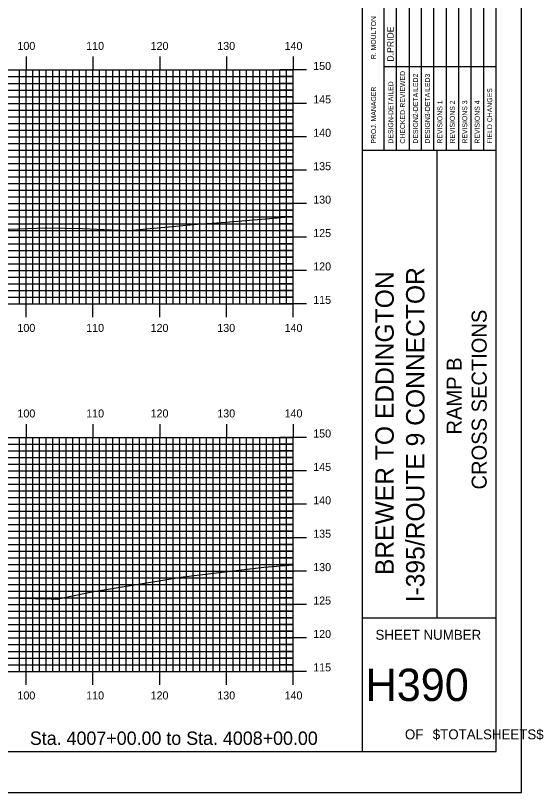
# Model space of a CAD drawing. Extents: x 851753 to 852097, y 364661 to 364881.
# Drawn here: x 852017.6 to 852096.7, y 364661.3 to 364777.5 of the extents above; entities that cross this region are included whole.
import ezdxf

# ---------------------------------------------------------------- set-up
doc = ezdxf.new("R2010")
doc.units = 0
for name, color, linetype in [('BORDER', 7, 'Continuous'), ('H_V ANNOTATION', 7, 'Continuous'), ('MAJOR', 7, 'Continuous'), ('MINOR', 7, 'Continuous'), ('PLOT BOUNDARY', 7, 'Continuous'), ('S_Roadway_Centerline', 7, 'Continuous')]:
    doc.layers.add(name, color=color, linetype=linetype)

msp = doc.modelspace()

# ---------------------------------------------------------------- linework, layer by layer
at = {"layer": 'BORDER'}
for p, q in [((852069.64, 364667.37), (852069.64, 364877.37)), ((852069.64, 364757.38), (852089.64, 364757.38)), ((852080.82, 364687.38), (852080.82, 364757.38)), ((852069.64, 364687.38), (852089.64, 364687.38))]:
    msp.add_line(p, q, dxfattribs=at)
msp.add_lwpolyline([(851769.64, 364667.37), (852089.64, 364667.37), (852089.64, 364877.37), (851769.64, 364877.37)], close=True, dxfattribs=at)
for points in [[(852074.74, 364757.38), (852074.74, 364792.38)], [(852076.6, 364792.38), (852076.6, 364757.38)], [(852078.46, 364757.38), (852078.46, 364792.38)], [(852080.33, 364757.38), (852080.33, 364792.38)], [(852082.19, 364757.38), (852082.19, 364792.38)], [(852084.05, 364757.38), (852084.05, 364792.38)], [(852085.92, 364757.38), (852085.92, 364792.38)], [(852087.78, 364757.38), (852087.78, 364792.38)], [(852072.87, 364757.38), (852072.87, 364790.96)], [(852072.87, 364769.88), (852089.64, 364769.88)]]:
    msp.add_lwpolyline(points, dxfattribs=at)
at = {"layer": 'MAJOR'}
for p, q in [((852019.24, 364771.37), (852019.24, 364769.37)), ((852029.24, 364771.37), (852029.24, 364769.37)), ((852039.24, 364771.37), (852039.24, 364769.37)), ((852049.24, 364771.37), (852049.24, 364769.37)), ((852059.24, 364771.37), (852059.24, 364769.37)), ((851779.24, 364769.37), (852059.24, 364769.37)), ((851779.24, 364769.37), (852059.24, 364769.37)), ((852019.24, 364734.37), (852019.24, 364769.37)), ((852029.24, 364734.37), (852029.24, 364769.37)), ((852039.24, 364734.37), (852039.24, 364769.37)), ((852049.24, 364734.37), (852049.24, 364769.37)), ((852061.25, 364769.37), (852057.24, 364769.37)), ((852059.24, 364734.37), (852059.24, 364769.37)), ((852059.24, 364734.37), (852059.24, 364769.37)), ((851779.24, 364764.37), (852059.24, 364764.37)), ((852061.25, 364764.37), (852057.24, 364764.37)), ((851779.24, 364759.37), (852059.24, 364759.37)), ((852061.25, 364759.37), (852057.24, 364759.37)), ((851779.24, 364754.37), (852059.24, 364754.37)), ((852061.25, 364754.37), (852057.24, 364754.37)), ((851779.24, 364749.37), (852059.24, 364749.37)), ((852061.25, 364749.37), (852057.24, 364749.37)), ((851779.24, 364744.37), (852059.24, 364744.37)), ((852061.25, 364744.37), (852057.24, 364744.37)), ((851779.24, 364739.37), (852059.24, 364739.37)), ((852061.25, 364739.37), (852057.24, 364739.37)), ((851779.24, 364734.37), (852059.24, 364734.37)), ((851779.24, 364734.37), (852059.24, 364734.37)), ((852019.24, 364732.37), (852019.24, 364734.37)), ((852029.24, 364732.37), (852029.24, 364734.37)), ((852039.24, 364732.37), (852039.24, 364734.37)), ((852049.24, 364732.37), (852049.24, 364734.37)), ((852061.25, 364734.37), (852057.24, 364734.37)), ((852059.24, 364732.37), (852059.24, 364734.37)), ((852019.24, 364716.37), (852019.24, 364714.37)), ((852029.24, 364716.37), (852029.24, 364714.37)), ((852039.24, 364716.37), (852039.24, 364714.37)), ((852049.24, 364716.37), (852049.24, 364714.37)), ((852059.24, 364716.37), (852059.24, 364714.37)), ((851779.24, 364714.37), (852059.24, 364714.37)), ((851779.24, 364714.37), (852059.24, 364714.37)), ((852019.24, 364679.37), (852019.24, 364714.37)), ((852029.24, 364679.37), (852029.24, 364714.37)), ((852039.24, 364679.37), (852039.24, 364714.37)), ((852049.24, 364679.37), (852049.24, 364714.37)), ((852061.25, 364714.37), (852057.24, 364714.37)), ((852059.24, 364679.37), (852059.24, 364714.37)), ((852059.24, 364679.37), (852059.24, 364714.37)), ((851779.24, 364709.37), (852059.24, 364709.37)), ((852061.25, 364709.37), (852057.24, 364709.37)), ((851779.24, 364704.37), (852059.24, 364704.37)), ((852061.25, 364704.37), (852057.24, 364704.37)), ((851779.24, 364699.37), (852059.24, 364699.37)), ((852061.25, 364699.37), (852057.24, 364699.37)), ((851779.24, 364694.37), (852059.24, 364694.37)), ((852061.25, 364694.37), (852057.24, 364694.37)), ((851779.24, 364689.37), (852059.24, 364689.37)), ((852061.25, 364689.37), (852057.24, 364689.37)), ((851779.24, 364684.37), (852059.24, 364684.37)), ((852061.25, 364684.37), (852057.24, 364684.37)), ((851779.24, 364679.37), (852059.24, 364679.37)), ((851779.24, 364679.37), (852059.24, 364679.37)), ((852019.24, 364677.37), (852019.24, 364679.37)), ((852029.24, 364677.37), (852029.24, 364679.37)), ((852039.24, 364677.37), (852039.24, 364679.37)), ((852049.24, 364677.37), (852049.24, 364679.37)), ((852061.25, 364679.37), (852057.24, 364679.37)), ((852059.24, 364677.37), (852059.24, 364679.37))]:
    msp.add_line(p, q, dxfattribs=at)
at = {"layer": 'MINOR'}
for p, q in [((851779.24, 364768.37), (852059.24, 364768.37)), ((852018.24, 364734.37), (852018.24, 364769.37)), ((852020.24, 364734.37), (852020.24, 364769.37)), ((852021.24, 364734.37), (852021.24, 364769.37)), ((852022.24, 364734.37), (852022.24, 364769.37)), ((852023.24, 364734.37), (852023.24, 364769.37)), ((852024.24, 364734.37), (852024.24, 364769.37)), ((852025.24, 364734.37), (852025.24, 364769.37)), ((852026.24, 364734.37), (852026.24, 364769.37)), ((852027.24, 364734.37), (852027.24, 364769.37)), ((852028.24, 364734.37), (852028.24, 364769.37)), ((852030.24, 364734.37), (852030.24, 364769.37)), ((852031.24, 364734.37), (852031.24, 364769.37)), ((852032.24, 364734.37), (852032.24, 364769.37)), ((852033.24, 364734.37), (852033.24, 364769.37)), ((852034.24, 364734.37), (852034.24, 364769.37)), ((852035.24, 364734.37), (852035.24, 364769.37)), ((852036.24, 364734.37), (852036.24, 364769.37)), ((852037.24, 364734.37), (852037.24, 364769.37)), ((852038.24, 364734.37), (852038.24, 364769.37)), ((852040.24, 364734.37), (852040.24, 364769.37)), ((852041.24, 364734.37), (852041.24, 364769.37)), ((852042.24, 364734.37), (852042.24, 364769.37)), ((852043.24, 364734.37), (852043.24, 364769.37)), ((852044.24, 364734.37), (852044.24, 364769.37)), ((852045.24, 364734.37), (852045.24, 364769.37)), ((852046.24, 364734.37), (852046.24, 364769.37)), ((852047.24, 364734.37), (852047.24, 364769.37)), ((852048.24, 364734.37), (852048.24, 364769.37)), ((852050.24, 364734.37), (852050.24, 364769.37)), ((852051.24, 364734.37), (852051.24, 364769.37)), ((852052.24, 364734.37), (852052.24, 364769.37)), ((852053.24, 364734.37), (852053.24, 364769.37)), ((852054.24, 364734.37), (852054.24, 364769.37)), ((852055.24, 364734.37), (852055.24, 364769.37)), ((852056.24, 364734.37), (852056.24, 364769.37)), ((852057.24, 364734.37), (852057.24, 364769.37)), ((852059.24, 364768.37), (852057.24, 364768.37)), ((852058.24, 364734.37), (852058.24, 364769.37)), ((851779.24, 364767.37), (852059.24, 364767.37)), ((852059.24, 364767.37), (852057.24, 364767.37)), ((851779.24, 364766.37), (852059.24, 364766.37)), ((852059.24, 364766.37), (852057.24, 364766.37)), ((851779.24, 364765.37), (852059.24, 364765.37)), ((852059.24, 364765.37), (852057.24, 364765.37)), ((851779.24, 364763.37), (852059.24, 364763.37)), ((852059.24, 364763.37), (852057.24, 364763.37)), ((851779.24, 364762.37), (852059.24, 364762.37)), ((851779.24, 364761.37), (852059.24, 364761.37)), ((852059.24, 364762.37), (852057.24, 364762.37)), ((852059.24, 364761.37), (852057.24, 364761.37)), ((851779.24, 364760.37), (852059.24, 364760.37)), ((852059.24, 364760.37), (852057.24, 364760.37)), ((851779.24, 364758.37), (852059.24, 364758.37)), ((852059.24, 364758.37), (852057.24, 364758.37)), ((851779.24, 364757.37), (852059.24, 364757.37)), ((852059.24, 364757.37), (852057.24, 364757.37)), ((851779.24, 364756.37), (852059.24, 364756.37)), ((852059.24, 364756.37), (852057.24, 364756.37)), ((851779.24, 364755.37), (852059.24, 364755.37)), ((852059.24, 364755.37), (852057.24, 364755.37)), ((851779.24, 364753.37), (852059.24, 364753.37)), ((852059.24, 364753.37), (852057.24, 364753.37)), ((851779.24, 364752.37), (852059.24, 364752.37)), ((852059.24, 364752.37), (852057.24, 364752.37)), ((851779.24, 364751.37), (852059.24, 364751.37)), ((852059.24, 364751.37), (852057.24, 364751.37)), ((851779.24, 364750.37), (852059.24, 364750.37)), ((852059.24, 364750.37), (852057.24, 364750.37)), ((851779.24, 364748.37), (852059.24, 364748.37)), ((852059.24, 364748.37), (852057.24, 364748.37)), ((851779.24, 364747.37), (852059.24, 364747.37)), ((851779.24, 364746.37), (852059.24, 364746.37)), ((852059.24, 364747.37), (852057.24, 364747.37)), ((852059.24, 364746.37), (852057.24, 364746.37)), ((851779.24, 364745.37), (852059.24, 364745.37)), ((852059.24, 364745.37), (852057.24, 364745.37)), ((851779.24, 364743.37), (852059.24, 364743.37)), ((852059.24, 364743.37), (852057.24, 364743.37)), ((851779.24, 364742.37), (852059.24, 364742.37)), ((852059.24, 364742.37), (852057.24, 364742.37)), ((851779.24, 364741.37), (852059.24, 364741.37)), ((852059.24, 364741.37), (852057.24, 364741.37)), ((851779.24, 364740.37), (852059.24, 364740.37)), ((852059.24, 364740.37), (852057.24, 364740.37)), ((851779.24, 364738.37), (852059.24, 364738.37)), ((852059.24, 364738.37), (852057.24, 364738.37)), ((851779.24, 364737.37), (852059.24, 364737.37)), ((852059.24, 364737.37), (852057.24, 364737.37)), ((851779.24, 364736.37), (852059.24, 364736.37)), ((852059.24, 364736.37), (852057.24, 364736.37)), ((851779.24, 364735.37), (852059.24, 364735.37)), ((852059.24, 364735.37), (852057.24, 364735.37)), ((852018.24, 364679.37), (852018.24, 364714.37)), ((852020.24, 364679.37), (852020.24, 364714.37)), ((852021.24, 364679.37), (852021.24, 364714.37)), ((852022.24, 364679.37), (852022.24, 364714.37)), ((852023.24, 364679.37), (852023.24, 364714.37)), ((852024.24, 364679.37), (852024.24, 364714.37)), ((852025.24, 364679.37), (852025.24, 364714.37)), ((852026.24, 364679.37), (852026.24, 364714.37)), ((852027.24, 364679.37), (852027.24, 364714.37)), ((852028.24, 364679.37), (852028.24, 364714.37)), ((852030.24, 364679.37), (852030.24, 364714.37)), ((852031.24, 364679.37), (852031.24, 364714.37)), ((852032.24, 364679.37), (852032.24, 364714.37)), ((852033.24, 364679.37), (852033.24, 364714.37)), ((852034.24, 364679.37), (852034.24, 364714.37)), ((852035.24, 364679.37), (852035.24, 364714.37)), ((852036.24, 364679.37), (852036.24, 364714.37)), ((852037.24, 364679.37), (852037.24, 364714.37)), ((852038.24, 364679.37), (852038.24, 364714.37)), ((852040.24, 364679.37), (852040.24, 364714.37)), ((852041.24, 364679.37), (852041.24, 364714.37)), ((852042.24, 364679.37), (852042.24, 364714.37)), ((852043.24, 364679.37), (852043.24, 364714.37)), ((852044.24, 364679.37), (852044.24, 364714.37)), ((852045.24, 364679.37), (852045.24, 364714.37)), ((852046.24, 364679.37), (852046.24, 364714.37)), ((852047.24, 364679.37), (852047.24, 364714.37)), ((852048.24, 364679.37), (852048.24, 364714.37)), ((852050.24, 364679.37), (852050.24, 364714.37)), ((852051.24, 364679.37), (852051.24, 364714.37)), ((852052.24, 364679.37), (852052.24, 364714.37)), ((852053.24, 364679.37), (852053.24, 364714.37)), ((852054.24, 364679.37), (852054.24, 364714.37)), ((852055.24, 364679.37), (852055.24, 364714.37)), ((852056.24, 364679.37), (852056.24, 364714.37)), ((852057.24, 364679.37), (852057.24, 364714.37)), ((852058.24, 364679.37), (852058.24, 364714.37)), ((851779.24, 364713.37), (852059.24, 364713.37)), ((852059.24, 364713.37), (852057.24, 364713.37)), ((851779.24, 364712.37), (852059.24, 364712.37)), ((851779.24, 364711.37), (852059.24, 364711.37)), ((852059.24, 364712.37), (852057.24, 364712.37)), ((852059.24, 364711.37), (852057.24, 364711.37)), ((851779.24, 364710.37), (852059.24, 364710.37)), ((852059.24, 364710.37), (852057.24, 364710.37)), ((851779.24, 364708.37), (852059.24, 364708.37)), ((852059.24, 364708.37), (852057.24, 364708.37)), ((851779.24, 364707.37), (852059.24, 364707.37)), ((852059.24, 364707.37), (852057.24, 364707.37)), ((851779.24, 364706.37), (852059.24, 364706.37)), ((852059.24, 364706.37), (852057.24, 364706.37)), ((851779.24, 364705.37), (852059.24, 364705.37)), ((852059.24, 364705.37), (852057.24, 364705.37)), ((851779.24, 364703.37), (852059.24, 364703.37)), ((852059.24, 364703.37), (852057.24, 364703.37)), ((851779.24, 364702.37), (852059.24, 364702.37)), ((852059.24, 364702.37), (852057.24, 364702.37)), ((851779.24, 364701.37), (852059.24, 364701.37)), ((852059.24, 364701.37), (852057.24, 364701.37)), ((851779.24, 364700.37), (852059.24, 364700.37)), ((852059.24, 364700.37), (852057.24, 364700.37)), ((851779.24, 364698.37), (852059.24, 364698.37)), ((852059.24, 364698.37), (852057.24, 364698.37)), ((851779.24, 364697.37), (852059.24, 364697.37)), ((851779.24, 364696.37), (852059.24, 364696.37)), ((852059.24, 364697.37), (852057.24, 364697.37)), ((852059.24, 364696.37), (852057.24, 364696.37)), ((851779.24, 364695.37), (852059.24, 364695.37)), ((852059.24, 364695.37), (852057.24, 364695.37)), ((851779.24, 364693.37), (852059.24, 364693.37)), ((852059.24, 364693.37), (852057.24, 364693.37)), ((851779.24, 364692.37), (852059.24, 364692.37)), ((852059.24, 364692.37), (852057.24, 364692.37)), ((851779.24, 364691.37), (852059.24, 364691.37)), ((852059.24, 364691.37), (852057.24, 364691.37)), ((851779.24, 364690.37), (852059.24, 364690.37)), ((852059.24, 364690.37), (852057.24, 364690.37)), ((851779.24, 364688.37), (852059.24, 364688.37)), ((852059.24, 364688.37), (852057.24, 364688.37)), ((851779.24, 364687.37), (852059.24, 364687.37)), ((852059.24, 364687.37), (852057.24, 364687.37)), ((851779.24, 364686.37), (852059.24, 364686.37)), ((852059.24, 364686.37), (852057.24, 364686.37)), ((851779.24, 364685.37), (852059.24, 364685.37)), ((852059.24, 364685.37), (852057.24, 364685.37)), ((851779.24, 364683.37), (852059.24, 364683.37)), ((851779.24, 364682.37), (852059.24, 364682.37)), ((852059.24, 364683.37), (852057.24, 364683.37)), ((852059.24, 364682.37), (852057.24, 364682.37)), ((851779.24, 364681.37), (852059.24, 364681.37)), ((852059.24, 364681.37), (852057.24, 364681.37)), ((851779.24, 364680.37), (852059.24, 364680.37)), ((852059.24, 364680.37), (852057.24, 364680.37))]:
    msp.add_line(p, q, dxfattribs=at)
at = {"layer": 'PLOT BOUNDARY'}
msp.add_lwpolyline([(851753.46, 364661.25), (852093.46, 364661.25), (852093.46, 364881.25), (851753.46, 364881.25)], close=True, dxfattribs=at)
at = {"layer": 'S_Roadway_Centerline'}
for points in [[(851950.37, 364751.21), (851968.79, 364746.7), (851973.85, 364745.71), (851977.69, 364745.58), (851991.46, 364744.81), (852007.78, 364745.28), (852009.57, 364745.32), (852010.8, 364745.36), (852022.36, 364745.73), (852027.69, 364745.64), (852031.99, 364745.46), (852034.87, 364745.34), (852035.13, 364745.39), (852044.9, 364746.3), (852049.13, 364746.6), (852059.24, 364747.43)], [(851940.2, 364700.18), (851940.49, 364700.08), (851940.56, 364700.06), (851940.95, 364699.91), (851957.44, 364692.86), (851965.87, 364691.92), (851977.86, 364690.69), (851987.91, 364690.56), (851992.17, 364690.5), (852003.7, 364690.4), (852008.58, 364690.52), (852022.99, 364690.23), (852023.93, 364690.19), (852024.96, 364690.42), (852029.08, 364691.28), (852042.76, 364693.52), (852054.82, 364694.96), (852059.24, 364695.34)]]:
    msp.add_lwpolyline(points, dxfattribs=at)

# ---------------------------------------------------------------- texts
at = {"layer": 'BORDER'}
for s, height, p in [('R. MOULTON', 0.745, (852071.65, 364770.98)), ('D.PRIDE', 0.969, (852074.29, 364770.62)), ('CHECKED-REVIEWED', 0.7455, (852076, 364758.35)), ('DESIGN2-DETAILED2', 0.7455, (852077.94, 364758.35)), ('DESIGN3-DETAILED3', 0.7455, (852079.73, 364758.35)), ('DESIGN-DETAILED', 0.7455, (852074.22, 364758.35)), ('PROJ. MANAGER', 0.7455, (852071.65, 364758.35)), ('FIELD CHANGES', 0.7455, (852089.05, 364758.35)), ('REVISIONS 1', 0.7455, (852081.59, 364758.35)), ('REVISIONS 2', 0.7455, (852083.46, 364758.35)), ('REVISIONS 3', 0.7455, (852085.32, 364758.35)), ('REVISIONS 4', 0.7455, (852087.18, 364758.35)), ('I-395/ROUTE 9 CONNECTOR', 2.7557, (852078.91, 364689.7)), ('BREWER TO EDDINGTON', 2.7557, (852074.31, 364693.78)), ('CROSS SECTIONS', 2.25, (852088.23, 364706.59)), ('RAMP B', 2.25, (852084.48, 364714.82))]:
    msp.add_text(s, height=height, rotation=90, dxfattribs=at).set_placement(p)
for s, height, p in [('SHEET NUMBER', 1.4905, (852071.57, 364684.1)), ('H390', 4.839, (852070.08, 364674.94)), ('OF', 1.491, (852075.98, 364669.2)), ('$TOTALSHEETS$', 1.4905, (852080.15, 364669.2))]:
    msp.add_text(s, height=height, dxfattribs=at).set_placement(p)
at = {"layer": 'H_V ANNOTATION'}
for s, height, p in [('100', 1.2, (852017.93, 364772.37)), ('110', 1.2, (852028.23, 364772.37)), ('120', 1.2, (852037.88, 364772.37)), ('130', 1.2, (852047.87, 364772.37)), ('140', 1.2, (852057.95, 364772.37)), ('150', 1.2, (852062.24, 364769.37)), ('145', 1.2, (852062.24, 364764.37)), ('140', 1.2, (852062.24, 364759.37)), ('135', 1.2, (852062.24, 364754.37)), ('130', 1.2, (852062.24, 364749.37)), ('125', 1.2, (852062.24, 364744.37)), ('120', 1.2, (852062.24, 364739.37)), ('115', 1.2, (852062.24, 364734.37)), ('100', 1.2, (852017.93, 364730.17)), ('110', 1.2, (852028.23, 364730.17)), ('120', 1.2, (852037.88, 364730.17)), ('130', 1.2, (852047.87, 364730.17)), ('140', 1.2, (852057.95, 364730.17)), ('100', 1.2, (852017.93, 364717.37)), ('110', 1.2, (852028.23, 364717.37)), ('120', 1.2, (852037.88, 364717.37)), ('130', 1.2, (852047.87, 364717.37)), ('140', 1.2, (852057.95, 364717.37)), ('150', 1.2, (852062.24, 364714.37)), ('145', 1.2, (852062.24, 364709.37)), ('140', 1.2, (852062.24, 364704.37)), ('135', 1.2, (852062.24, 364699.37)), ('130', 1.2, (852062.24, 364694.37)), ('125', 1.2, (852062.24, 364689.37)), ('120', 1.2, (852062.24, 364684.37)), ('115', 1.2, (852062.24, 364679.37)), ('100', 1.2, (852017.93, 364675.17)), ('110', 1.2, (852028.23, 364675.17)), ('120', 1.2, (852037.88, 364675.17)), ('130', 1.2, (852047.87, 364675.17)), ('140', 1.2, (852057.95, 364675.17)), ('Sta. 4007+00.00 to Sta. 4008+00.00', 2.0004, (852019.79, 364668.37))]:
    msp.add_text(s, height=height, dxfattribs=at).set_placement(p)

doc.saveas('drawing.dxf')
